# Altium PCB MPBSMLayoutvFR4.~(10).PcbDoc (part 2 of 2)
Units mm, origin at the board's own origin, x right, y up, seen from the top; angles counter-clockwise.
Board outline 131.7 x 110.39 mm, 4 copper layers (Top Layer, Power, GroundPlane, Bottom Layer), stack 2.286 mm thick; 156 components, 77 nets, 429 pads, 117 vias.
Unrouted connection lines stored in the file: 25.
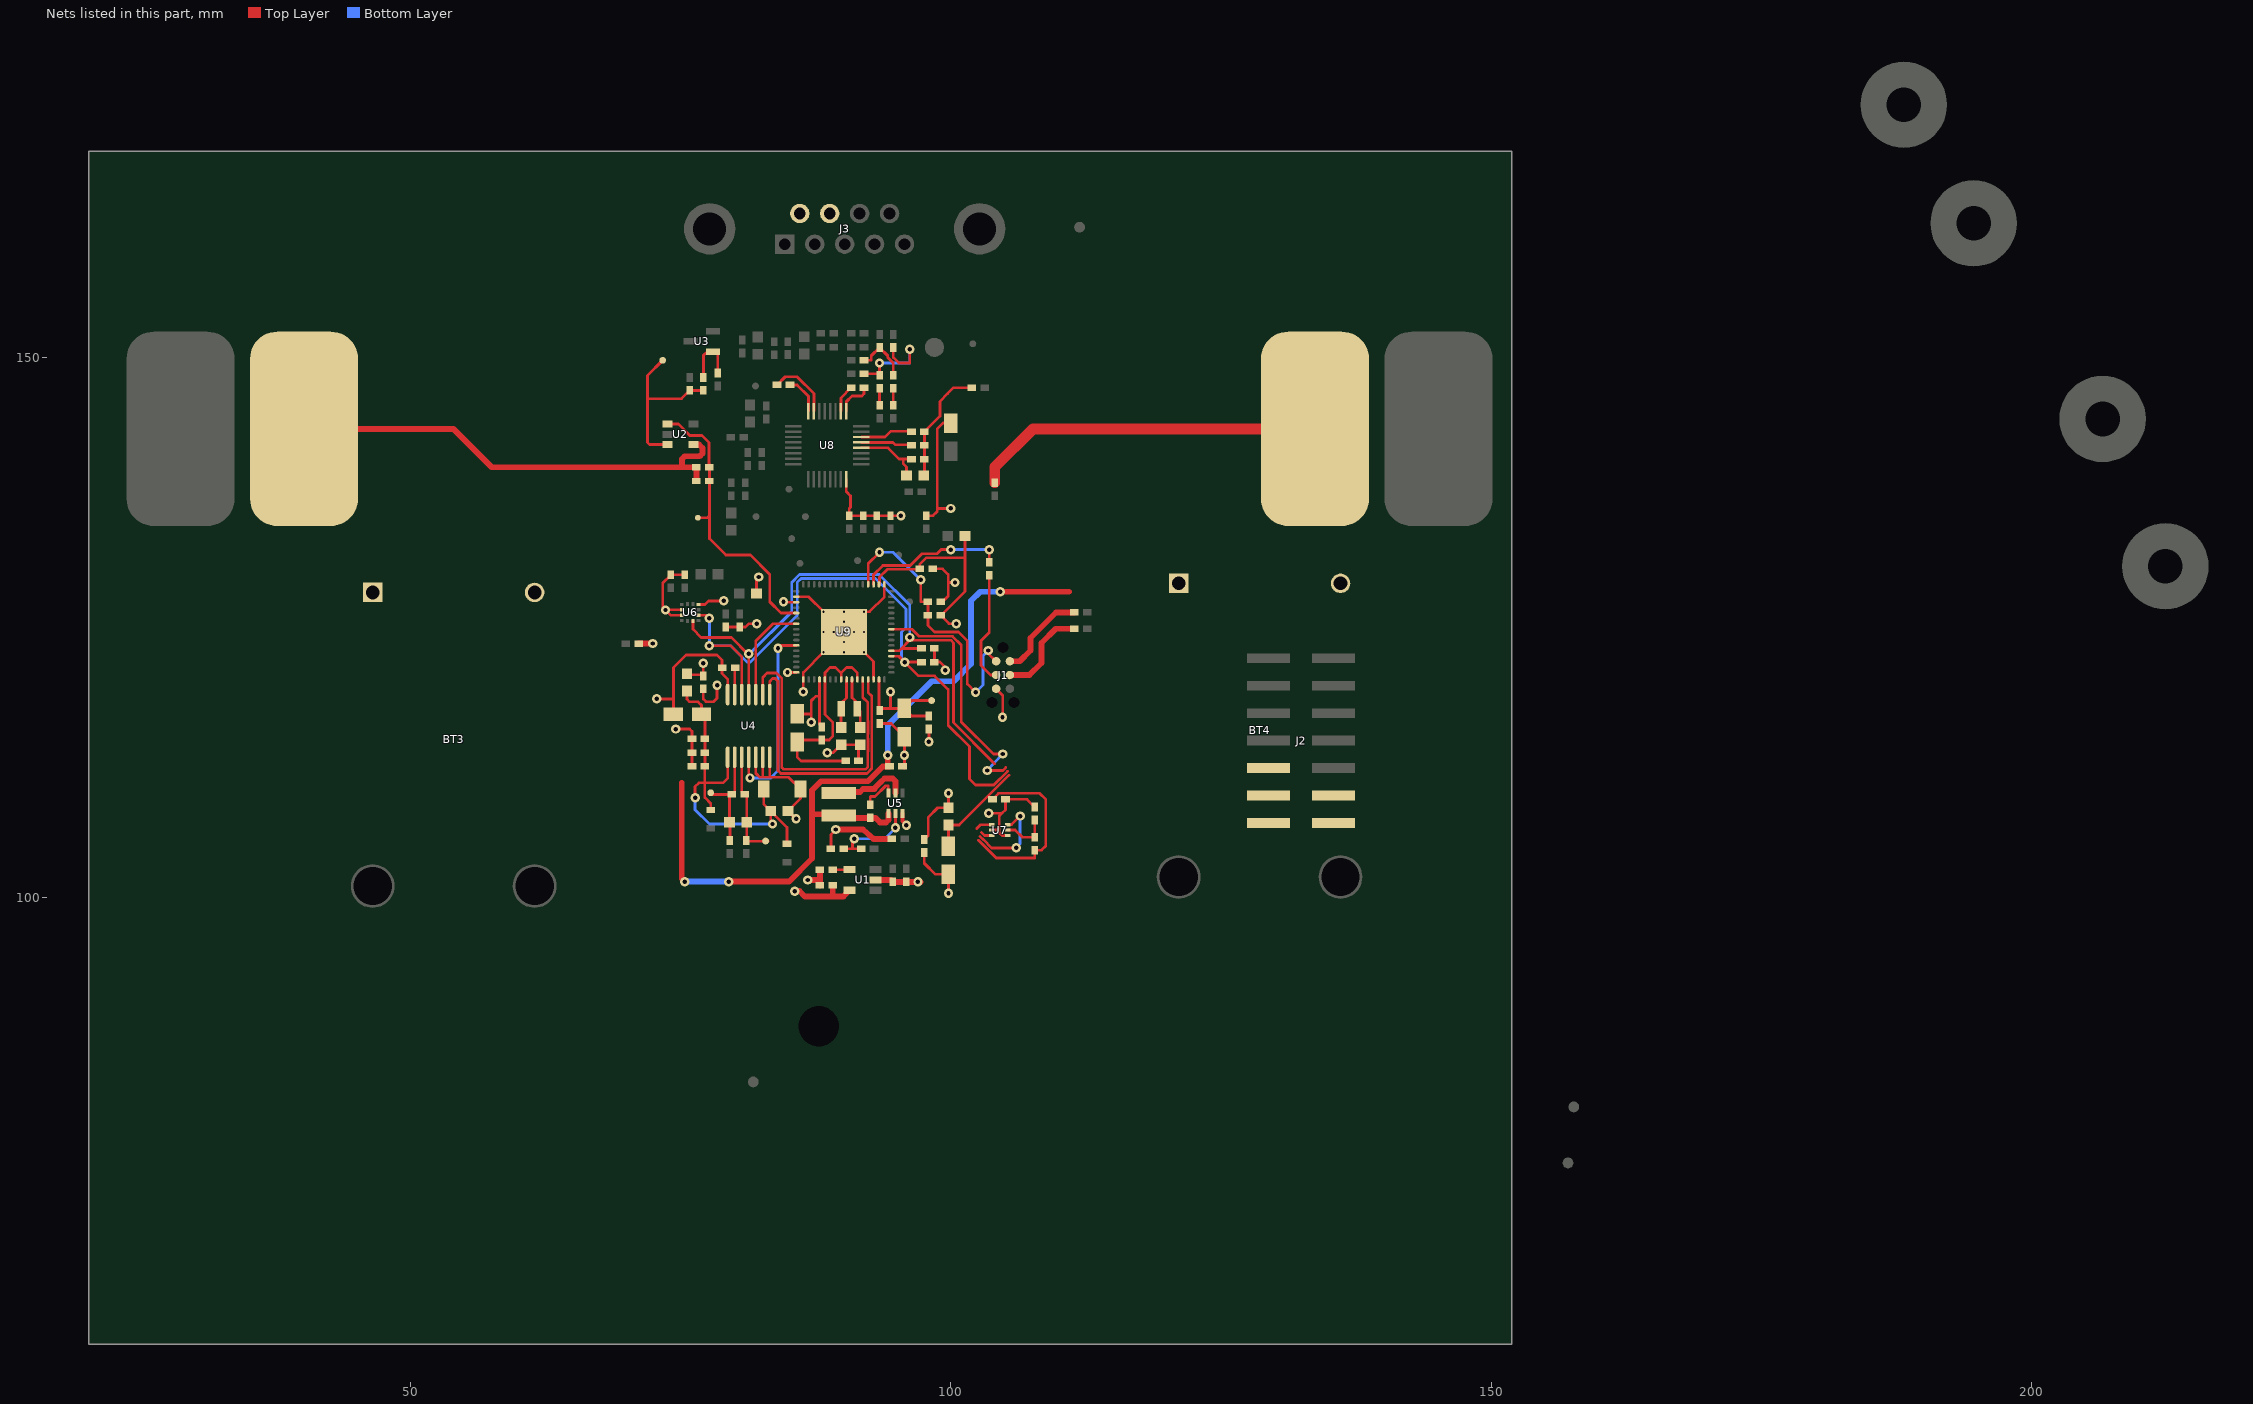
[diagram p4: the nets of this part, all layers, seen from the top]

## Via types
v1: diameter 0.864, hole 0.406, Top Layer to Bottom Layer, 104 vias
v2: diameter 0.5, hole 0.2, Top Layer to Bottom Layer, 13 vias

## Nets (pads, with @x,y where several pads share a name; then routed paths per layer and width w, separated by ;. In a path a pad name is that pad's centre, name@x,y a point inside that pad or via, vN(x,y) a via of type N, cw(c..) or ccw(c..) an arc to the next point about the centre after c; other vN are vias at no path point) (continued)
BOOST_INPUT: BT3.1 BT4.1 C34.1 L7.1 R16.1 U5.1 | length 73.3
  Top Layer w0.254: L7.1@89.612,107.681 L7.1@89.621,107.672 ; v1(94.158,113.132) v1@94.32,112.97
  Top Layer w0.5: 75.108,110.592 75.108,101.702 v1(75.362,101.448)
  Top Layer w0.54: v1(79.426,101.448) 85.014,101.448 87.147,103.581 87.147,109.906 87.986,110.744 92.329,110.744 93.701,112.116 C34.1@94.32,112.116 ; 87.147,107.696 L7.1@89.612,107.681 ; L7.1@89.832,107.35 R16.1@92.532,107.35 93.018,107.35 93.434,106.934 94.005,106.934 94.219,107.148 U5.1@94.219,107.762 ; C34.1@94.158,112.278 v1(94.158,113.132) ; v1(104.572,128.287) 110.921,128.287
  Bottom Layer w0.54: v1(75.362,101.448) v1(79.426,101.448) ; v1(94.158,113.132) 94.158,115.926 98.222,119.99 100.254,119.99 101.87,121.606 101.87,127.448 102.709,128.287 v1(104.572,128.287)
DVCC: 1.1 C1.1 C5.1 C6.1 C10.1 C14.1 C18.1 L1.1 L2.1 L3.1 L5.1 R1.1 R6.2 R31.1 R32.1 U1.5 U9.18 U9.35 U9.48 U9.63 | length 53
  Top Layer w0.254: L1.1@75.362,120.59 76.94,120.59 C10.1@76.964,120.613 ; C10.1@77.089,120.488 v1(77.089,121.666) ; L3.1@82.004,128.118 82.004,129.426 v1(82.22,129.642) ; v1@84.55,127.312 U9.35@85.694,127.312 ; v1(84.876,120.812) U9.48@85.694,120.812 ; U9.63@93.345,120.162 93.345,117.339 C6.1@93.396,117.288 ; U9.18@93.345,128.962 93.391,129.008 93.391,129.637 94.11,130.356 97.066,130.356 C18.1@97.114,130.404 97.114,130.82 97.714,131.42 101.27,131.42 ; C6.1@93.588,117.48 C1.1@95.682,117.48 ; 94.415,117.483 v1(94.415,119.027) ; C14.1@97.538,105.35 97.917,105.728 97.917,107.414 98.788,108.286 L2.1@99.779,108.286 v1(99.779,109.621) ; R1.1@97.968,116.78 96.382,116.78 C1.1@95.682,117.48 ; 1.1@98.222,118.212 96.414,118.212 C1.1@95.682,117.48 ; R32.1@98.476,123.038 R31.1@98.476,121.768 98.984,121.768 99.492,121.26 v1(99.492,121.006) ; v1(100.508,125.324) 99.838,125.324 R6.2@99.076,126.086 101.308,128.318 L5.1@101.308,133.452
  Top Layer w0.54: v1(85.547,100.559) v1@85.954,100.559 ; 85.979,100.584 86.487,100.076 89.073,100.076 ; C5.1@89.073,101.092 89.073,100.076 ; U1.5@90.621,100.65 90.047,100.076 89.073,100.076
  other v1: 84.506,127.356
EL_GSR1: C26.2 J3.7 R10.1 TP2.1 U2.4 | length 43.3
  Top Layer w0.254: U2.4@76.17,141.9 76.682,141.9
  Top Layer w0.54: TP2.1@40.132,143.358 53.95,143.358 57.506,139.802 R10.1@76.448,139.802 C26.2@76.448,138.532 ; 75.108,139.852 75.108,140.564 75.362,140.818 76.748,140.818 77.002,141.072 77.002,141.58 76.682,141.9
EL_GSR2: J3.6 R9.2 TP1.1 | length 32.6
  Top Layer w1: R9.2@104.064,138.37 104.064,139.827 107.594,143.358 TP1.1@133.706,143.358
GND: BT3.2 BT4.2 C1.2 C3.2 C4.2 C5.2 C6.2 C8.2 C9.2 C10.2 C11.2 C12.2 C13.2 C14.2 C15.2 C16.2 C17.2 C18.2 C19.2 C20.2 C21.2 C25.2 C27.2 C28.2 C29.1 C32.2 C33.2 C34.2 C35.2 C36.2 C37.2 C38.2 C41.2 C42.2 C58.2 C59.2 J1.6 J2.6 R2.1 R3.1 R17.1 U1.2 U4.5 U4.6 U4.7 U4.14 U5.3 U6.4 U6.8 U6.9 U7.2 U7.4 U8.24 U9.17 U9.34 U9.49 U9.62 U9.65 | length 145.9
  Top Layer w0.254: v1(72.771,118.364) 74.316,118.364 ; C9.2@74.316,116.942 74.316,118.364 ; v1(74.549,115.57) 75.819,115.57 76.032,115.357 C27.2@76.032,114.656 C11.2@76.032,113.386 C28.2@76.032,112.116 ; U6.9@75.095,126.111 74.067,126.111 v1(73.584,126.594) ; U6.8@75.095,126.611 73.601,126.611 v1(73.584,126.594) ; C37.2@75.362,129.847 C16.2@74.092,129.847 73.33,129.085 73.33,126.848 v1(73.584,126.594) ; U6.4@76.645,127.111 77.249,127.111 77.571,127.433 v1(78.99,127.433) ; C10.2@77.089,119.288 77.089,118.364 77.343,118.11 78.047,118.11 78.359,118.422 v1(78.359,119.634) ; C36.2@79.172,125.024 C17.2@80.442,125.024 80.997,125.024 81.297,125.324 v1(82.042,125.324) ; U4.14@79.337,118.764 79.337,120.193 78.826,120.704 C29.1@78.826,121.26 78.826,121.961 78.359,122.428 75.484,122.428 74.316,121.26 74.316,118.364 ; U4.5@81.937,112.964 81.937,111.484 82.321,111.1 83.236,111.1 ; 82.587,111.137 U4.6@82.587,112.964 ; U4.7@83.237,112.964 83.236,111.1 ; v1(85.67,107.266) 85.645,107.266 C33.2@84.92,107.991 86.074,109.145 C32.2@86.074,110.023 84.997,111.1 83.236,111.1 ; U9.34@85.694,127.812 86.844,127.812 v2(88.219,126.437) v2(90.094,124.562) ; v1(86.343,119.033) U9.49@86.343,120.162 86.343,120.811 v2(88.219,122.687) v2(90.094,124.562) ; v1(86.741,101.6) v1@86.754,101.613 ; v1(88.57,113.386) 89.116,113.386 89.84,114.11 C58.2@91.618,114.11 ; R17.1@88.894,104.496 88.894,105.812 v1(89.356,106.274) ; U8.24@90.32,138.704 90.32,137.544 90.702,137.162 90.702,136.099 90.602,135.999 C42.2@90.602,135.322 C41.2@91.872,135.322 C19.2@93.142,135.322 C20.2@94.412,135.322 v1@95.317,135.322 ; R2.1@91.456,112.624 C58.2@91.456,113.948 ; U9.62@92.844,120.162 92.844,121.811 v2(91.969,122.687) v2(90.094,124.562) ; C6.2@93.396,115.888 C6.2@93.396,116.088 94.474,116.088 C1.2@95.682,114.88 95.7,114.861 v1(95.7,113.132) 95.7,112.296 C34.2@95.52,112.116 C34.2@95.682,111.954 ; U9.17@93.845,128.962 93.845,127.805 92.477,126.437 v2(91.969,126.437) v2(90.094,124.562) ; C3.2@94.447,101.6 C3.2@94.62,101.428 ; v1(96.952,101.448) 96.952,101.194 v1@97.186,101.428 ; C14.2@97.538,104.15 97.538,103.147 98.564,102.122 C12.2@99.779,102.122 v1(99.779,100.374) ; C21.2@97.714,135.322 98.365,135.322 98.73,135.687 98.73,143.358 99.268,143.896 C15.2@100,143.896 C15.2@100,144.374 ; C18.2@98.314,130.404 99.238,130.404 99.746,129.896 99.746,129.134 ; 98.73,135.992 v1(100,135.992) ; C25.2@99.076,127.356 99.238,127.356 99.746,127.864 99.746,129.134 ; v1(100.381,129.134) 99.746,129.134 ; v1(103.5,107.783) 104.745,107.783 ; U7.2@103.779,106.221 104.449,106.221 ; J1.6@104.191,119.304 104.8,118.694 104.8,116.688 v1(104.775,116.662) ; U7.4@105.279,105.721 104.724,105.721 104.474,105.971 104.474,107.512 104.745,107.783 ; C38.2@107.757,108.352 107.041,109.068 C13.2@105.055,109.068 105.055,108.093 104.745,107.783
  Top Layer w0.354: U5.3@95.519,107.762 95.519,107.046 v1(95.885,106.68)
  Top Layer w0.54: R3.1@71.094,123.489 v1(72.397,123.489) ; v1@86.754,101.613 87.873,101.613 ; C5.2@87.873,101.092 87.873,101.613 ; C8.2@87.873,102.54 87.873,101.613 ; v1(89.356,106.274) 90.672,106.274 91.872,106.274 92.837,105.41 C35.2@94.573,105.41 ; U1.2@93.021,101.6 C3.2@94.447,101.6 ; C3.2@94.62,101.428 C4.2@95.89,101.428 v1@97.186,101.428
  other v1: 95.377,135.322
  other v2: 90.094,122.687 90.094,123.624 88.219,124.562 89.156,124.562 91.031,124.562 91.969,124.562 90.094,125.499 90.094,126.437
GSR_ANALOG_OUTPUT: 2.1 C26.1 R10.2 U2.1 U9.37 | length 26.9
  Top Layer w0.254: U2.1@73.77,143.8 74.776,143.8 75.828,142.748 76.945,142.748 77.606,142.088 77.606,140.14 77.648,140.098 R10.2@77.648,139.802 C26.1@77.648,138.532 77.648,135.23 ; 2.1@76.581,135.128 77.546,135.128 ; 77.546,135.23 77.648,135.23 ; U9.37@85.694,126.312 84.28,126.312 83.236,127.356 83.236,129.896 81.458,131.674 79.172,131.674 77.648,133.198 77.648,135.23
JTAG_TCK: J1.4 J2.4 R7.1 | length 10.4
  Top Layer w0.254: R7.1@103.556,129.804 103.556,124.511 102.794,123.749 102.794,121.463 103.683,120.574 J1.4@104.191,120.574
JTAG_TDO/TDI: C25.1 J1.2 J2.2 R6.1 U9.20 | length 28.1
  Top Layer w0.254: U9.20@92.344,128.962 92.344,130.876 v1(93.396,131.928) ; v1(97.206,129.388) 97.206,127.356 C25.1@97.876,127.356 R6.1@97.876,126.086 97.876,125.162 98.476,124.562 100.702,124.562 101.524,123.74 101.524,119.736 v1(102.286,118.974) ; v1(103.454,122.843) 103.454,122.58 J1.2@104.191,121.844
  Bottom Layer w0.254: v1(93.396,131.928) 94.666,131.928 v1(97.206,129.388) ; v1(102.286,118.974) 102.972,119.659 102.972,122.36 v1(103.454,122.843)
JTAG_TEST/SBWTCK: R7.2 U9.19 | length 13.7
  Top Layer w0.254: U9.19@92.844,128.962 92.844,129.852 93.702,130.71 96.242,130.71 97.333,131.801 98.728,131.801 99.109,132.182 v1(100,132.182) ; R7.2@103.556,131.004 v1(103.556,132.182)
  Bottom Layer w0.254: v1(100,132.182) v1(103.556,132.182)
JTAG_VCC_TARGET_IN: J1.3 J2.3 R5.1 | length 8.8
  Top Layer w0.54: J1.3@105.461,120.574 107.264,120.574 108.382,121.691 108.382,122.707 108.382,123.546 109.697,124.861 R5.1@111.433,124.861
JTAG_VCC_TOOL_OUT: J1.1 J2.1 R4.1 | length 8.5
  Top Layer w0.54: J1.1@105.461,121.844 106.375,121.844 107.366,122.834 107.366,124.003 109.728,126.365 R4.1@111.414,126.365
MSP_AVCC: C2.1 C7.1 R1.2 U9.52 | length 9.3
  Top Layer w0.254: C2.1@86.095,116.972 87.076,116.972 ; v1(87.076,116.21) 87.076,116.972 ; C7.1@87.843,115.982 87.843,118.618 ; U9.52@87.843,120.162 87.843,118.618 ; v1(97.968,114.402) R1.2@97.968,115.58 ; 87.076,116.972 87.076,118.191 87.503,118.618 87.843,118.618
MSP_AVSS: C2.2 C7.2 R2.2 U9.53 U9.56 U9.59 | length 20.5
  Top Layer w0.254: C2.2@85.776,114.372 85.776,112.979 86.131,112.624 R2.2@90.256,112.624 ; C2.2@85.968,114.564 C7.2@88.062,114.564 88.732,114.564 89.078,114.91 89.078,116.18 88.343,116.914 U9.53@88.343,120.162 88.343,120.779 88.824,121.26 89.332,121.26 89.836,120.756 ; U9.56@89.844,120.162 89.844,120.756 90.348,121.26 90.856,121.26 91.344,120.771 U9.59@91.344,120.162
MSP_LFXIN: C59.1 U9.57 Y1.1 | length 4.1
  Top Layer w0.254: C59.1@89.84,115.71 89.84,117.438 Y1.1@89.852,117.45 ; Y1.1@89.852,117.97 90.344,118.462 U9.57@90.344,120.162
MSP_LFXOUT: C58.1 U9.58 Y1.2 | length 4.3
  Top Layer w0.254: U9.58@90.844,120.162 90.844,118.477 Y1.2@91.352,117.97 ; Y1.2@91.352,117.45 91.618,117.184 C58.1@91.618,115.71
MSP_P1.0_INT: U4.10 U9.39 | length 9.4
  Top Layer w0.254: U4.10@81.937,118.764 81.937,123.749 ; 81.952,123.749 83.515,125.312 U9.39@85.694,125.312
MSP_P2.7_INT: U7.3 U9.9 | length 24.2
  Top Layer w0.254: U9.9@94.494,124.812 96.417,124.812 97.075,124.154 100.154,124.154 100.962,123.346 100.962,116.234 103.937,113.259 v1(104.8,113.259) ; 102.841,105.989 103.109,105.721 U7.3@103.779,105.721 ; v1@103.361,111.743 104.822,111.743 105.09,112.011
  Bottom Layer w0.254: v1(103.353,111.735) v1(104.8,113.259)
MSP_P4.0_INT: U4.9 U9.60 | length 28.4
  Top Layer w0.254: U4.9@82.587,118.764 82.587,120.356 82.982,120.752 83.849,120.752 84.352,120.248 84.352,112.016 84.506,111.862 92.126,111.862 92.31,112.046 92.31,113.506 92.32,113.516 92.32,114.704 92.31,114.713 92.31,115.106 92.32,115.116 92.32,116.304 92.31,116.313 92.31,118.027 91.844,118.493 U9.60@91.844,120.162
MSP_P4.1_INT: U4.8 U9.61 | length 27.8
  Top Layer w0.254: U4.8@83.237,118.764 83.237,119.99 83.49,120.244 83.744,120.244 83.998,119.99 83.998,111.718 84.262,111.454 92.226,111.454 ; 92.226,111.461 92.664,111.9 92.664,113.36 92.674,113.369 92.674,118.612 92.344,118.942 U9.61@92.344,120.162
MSP_P9.3_OUT: U4.4 U9.43 | length 18
  Top Layer w0.254: U4.4@81.287,112.964 81.287,111.169 v1(81.407,111.049) ; v1(83.998,123.038) 84.272,123.312 U9.43@85.694,123.312
  Bottom Layer w0.254: v1(81.407,111.049) 83.329,111.049 83.998,111.718 v1(83.998,123.038)
MSP_UCB0SCL_TMP103_SCL_RF430CL330HCPW_SCL: R32.2 U4.11 U6.12 U7.1 U9.5 | length 56.8
  Top Layer w0.254: U6.12@76.12,125.586 76.12,124.82 76.886,124.054 79.68,124.054 v1@81.236,122.497 ; U4.11@81.287,118.764 v1@81.287,122.447 ; U9.5@94.494,122.812 95.202,122.812 95.428,123.038 ; v1(96.19,124.054) v1@96.19,123.8 ; R32.2@97.114,123.038 95.428,123.038 ; 102.391,106.343 102.768,106.721 U7.1@103.779,106.721 ; 104.044,112.365 103.861,112.547 100.254,116.18 100.254,123.546 100,123.8 v1@96.19,123.8 ; 95.428,123.038 v1@96.19,123.8
  Bottom Layer w0.254: v1(81.278,122.539) 81.287,122.531 81.287,122.447 85.268,126.428 85.268,129.134 86,129.866 93.365,129.866 96.19,127.042 v1(96.19,124.054)
MSP_UCB0SDA_TMP103_SDA_RF430CL330HCPW_SDA: R31.2 U4.12 U6.2 U7.6 U9.4 | length 70.6
  Top Layer w0.254: U6.2@76.645,126.111 77.369,126.111 v1(77.648,125.832) ; v1(77.648,123.292) 79.594,123.292 80.653,122.233 80.653,118.78 U4.12@80.637,118.764 ; U9.4@94.494,122.312 95.174,122.312 v1(95.718,121.768) ; R31.2@97.276,121.768 v1(95.718,121.768) ; 102.694,105.635 102.998,105.332 103.005,105.332 103.767,104.57 v1(106.053,104.57) ; 105.236,111.657 103.968,110.388 102.286,110.388 101.714,110.96 101.714,113.957 99.746,115.926 99.746,119.228 98.476,120.498 96.988,120.498 v1(95.718,121.768) ; U7.6@105.279,106.721 105.613,106.721 v1(106.409,107.516)
  Bottom Layer w0.254: v1(77.648,125.832) v1(77.648,123.292) 79.594,123.292 81.118,121.768 81.458,121.768 85.776,126.086 85.776,129.134 86.154,129.512 93.017,129.512 95.836,126.694 95.836,124.97 95.428,124.562 95.428,122.058 v1(95.718,121.768) ; v1(106.053,104.57) 106.409,104.925 v1(106.409,107.516)
Net3_1: 3.1 R11.1 R12.2 U2.3 | length 15.6
  Top Layer w0.254: 71.922,146.152 75.059,146.152 R12.2@75.824,146.917 R11.1@77.094,146.917 ; 3.1@73.33,149.708 71.922,148.3 71.922,142.088 72.11,141.9 U2.3@73.77,141.9
Net4_1: 4.1 C30.1 C31.1 R13.1 U4.2 | length 9.9
  Top Layer w0.254: 4.1@77.77,109.676 77.932,109.515 C31.1@79.71,109.515 ; R13.1@79.548,105.255 79.548,106.903 C30.1@79.51,106.941 79.51,109.315 C31.1@79.71,109.515 ; U4.2@79.987,112.964 79.987,109.791 C31.1@79.71,109.515
Net5_1: 5.1 C30.2 C31.2 R14.1 U4.3 | length 9.9
  Top Layer w0.254: U4.3@80.637,112.964 80.637,109.788 C31.2@80.91,109.515 81.11,109.315 C30.2@81.11,106.941 81.11,105.293 81.207,105.197 5.1@83.104,105.197
NetC8_1: C8.1 U1.4 | length 1.6
  Top Layer w0.254: C8.1@89.068,102.54 89.078,102.55 U1.4@90.621,102.55
NetC29_2: C29.2 U4.13 | length 2.5
  Top Layer w0.254: U4.13@79.987,118.764 79.987,121.22 C29.2@80.026,121.26
NetC38_1: C38.1 R18.1 U7.5 | length 4.3
  Top Layer w0.254: U7.5@105.279,106.221 105.951,106.221 106.615,105.558 R18.1@107.757,105.558 C38.1@107.757,107.152
NetC43_1: C43.1 R19.2 R20.2 R21.2 R22.1 | length 10.9
  Top Layer w0.254: C43.1@97.552,139.094 R20.2@97.552,140.564 R21.2@97.552,141.834 97.552,141.876 R19.2@97.552,143.104 98.984,144.536 98.984,145.898 99.704,146.618 100.254,147.168 R22.1@101.94,147.168
NetC43_2: C43.2 R20.1 U8.28 | length 6.7
  Top Layer w0.254: U8.28@91.719,141.603 94.172,141.603 95.212,140.564 95.58,140.564 ; C43.2@95.898,139.04 95.898,139.818 95.58,140.135 95.58,140.564 ; R20.1@96.352,140.564 95.58,140.564
NetC45_1: C45.1 U8.2 | length 2.6
  Top Layer w0.254: U8.2@89.82,145.003 89.82,146.224 C45.1@90.764,147.168
NetC45_2: C45.2 U8.1 | length 3.4
  Top Layer w0.254: U8.1@90.32,145.003 90.32,145.87 90.856,146.406 91.757,146.406 91.964,146.612 C45.2@91.964,147.168
NetC46_2: C46.2 C48.2 C49.2 | length 10.4
  Top Layer w0.254: C46.2@91.964,148.45 C49.2@93.267,148.45 ; C49.2@93.396,148.322 v1(93.396,149.454) ; C48.2@94.666,150.886 94.671,150.88 94.671,149.967 95.185,149.454 96.19,149.454 v1(96.19,150.724)
  Bottom Layer w0.254: v1(93.396,149.454) 96.19,149.454 v1(96.19,150.724)
NetC47_1: C47.1 U8.8 | length 3.5
  Top Layer w0.254: C47.1@85.106,147.422 85.776,147.422 86.82,146.378 U8.8@86.82,145.003
NetC47_2: C47.2 U8.7 | length 6
  Top Layer w0.254: C47.2@83.906,147.422 84.668,148.184 85.776,148.184 87.32,146.64 U8.7@87.32,145.003
NetC49_1: C49.1 R26.1 | length 1.6
  Top Layer w0.254: R26.1@93.396,145.528 C49.1@93.396,147.122
NetC52_2: C52.2 C53.2 C54.2 | length 5.3
  Top Layer w0.254: C54.2@91.964,149.708 92.634,149.708 92.634,150.124 C52.2@93.396,150.886 94.158,150.124 94.158,149.962 94.666,149.454 C53.2@94.666,148.322
NetC53_1: C53.1 R27.1 | length 1.6
  Top Layer w0.254: R27.1@94.666,145.528 C53.1@94.666,147.122
NetL7_2: L7.2 U5.5 | length 5.5
  Top Layer w0.254: 92.939,110.033 92.939,110.084
  Top Layer w0.54: L7.2@91.059,109.752 91.591,109.752 91.872,110.033 92.939,110.033 ; 92.939,110.084 93.519,110.664 93.853,110.998 94.615,110.998 94.869,110.744 U5.5@94.869,109.662
NetR8_1: R8.1 R11.2 U3.1 | length 5.5
  Top Layer w0.254: R11.2@77.094,148.117 77.094,150.17 77.46,150.536 78.41,150.536 R8.1@78.41,148.53
NetR15_1: R15.1 R17.2 U5.2 | length 8.1
  Top Layer w0.254: R17.2@90.094,104.496 90.891,104.496 ; v1(91.059,105.41) 90.891,105.242 90.891,104.496 ; R15.1@91.688,104.496 90.891,104.496 ; v1(94.869,106.426) U5.2@94.869,107.762
  Bottom Layer w0.254: v1(91.059,105.41) 93.853,105.41 v1(94.869,106.426)
NetR16_2: R16.2 U5.6 | length 3.5
  Top Layer w0.254: R16.2@92.532,108.55 92.532,109.271 92.583,109.322 92.964,109.322 93.969,110.327 94.209,110.327 94.209,109.672 U5.6@94.219,109.662
NetR19_1: R19.1 U8.30 | length 4.9
  Top Layer w0.254: U8.30@91.719,142.603 93.911,142.603 94.454,143.146 R19.1@96.352,143.146
NetR21_1: R21.1 U8.29 | length 4.7
  Top Layer w0.254: U8.29@91.719,142.103 94.65,142.103 94.878,141.876 R21.1@96.352,141.876
RF430_DVCC: C9.1 C11.1 C27.1 C28.1 C32.1 C33.1 D1.1 D2.1 L1.2 U4.1 | length 34
  Top Layer w0.254: 75.565,118.512 75.565,118.338 75.811,118.092 76.599,118.092 76.916,117.775 C9.1@76.916,116.942 C9.1@77.14,117.166 ; v1(76.327,109.22) 76.327,110.236 76.683,110.592 77.226,110.592 ; C28.1@77.232,112.116 C11.1@77.232,113.386 C27.1@77.232,114.656 C9.1@77.232,116.626 ; C28.1@77.324,112.024 77.226,111.926 77.226,110.592 ; D1.1@77.77,108.079 77.77,108.691 77.226,109.235 77.226,110.592 ; U4.1@79.337,112.964 79.337,111.01 78.918,110.592 77.226,110.592 ; C32.1@82.674,110.023 82.674,108.637 C33.1@83.32,107.991 ; v1(83.49,106.782) 83.32,106.951 C33.1@83.32,107.991 ; D2.1@84.836,104.989 84.836,106.475 C33.1@83.32,107.991
  Bottom Layer w0.254: v1(76.327,109.22) 76.327,108.102 77.648,106.782 v1(83.49,106.782)
TMP_DVCC: C12.1 C13.1 L2.2 R18.2 | length 27
  Top Layer w0.254: C12.1@99.779,104.722 L2.2@99.779,106.686 100.766,106.686 105.383,111.303 ; 102.548,105.281 104.199,103.63 107.757,103.63 R18.2@107.757,104.358 108.381,104.358 108.792,104.768 108.792,109.049 108.223,109.618 104.405,109.618 C13.1@103.855,109.068
pads on no net: BT3.3 BT3.4 BT4.3 BT4.4 FID1.1 FID2.1 FID3.1 H1.0 H2.0 H3.0 H4.0 H5.1 H6.1 H7.1 H8.1 H9.0 H10.0 H11.0 H12.0 J1.5 J1.MH1 J1.MH2 J1.MH3 J2.5 J2.7 J2.8 J2.9 J2.10 J2.11 J2.12 J2.13 J2.14 J3.3 J3.5 J3.8 J3.9 U3.3 U6.10 U8.17 U9.1 U9.2 U9.3 U9.6 U9.7 U9.8 U9.10 U9.11 U9.12 U9.13 U9.15 U9.21 U9.22 U9.23 U9.24 U9.36 U9.40 U9.41 U9.42 U9.44 U9.45 U9.46 U9.47 U9.50 U9.51 U9.54 U9.55 U9.64
copper on no net: | length 0.5
  Top Layer w0.254: 104.521,124.206 v1(104.521,124.714)

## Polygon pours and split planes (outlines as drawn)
DVCC on Power (split plane): 102.41,142.288 102.41,131.727 101.775,131.092 78.667,131.092 78.031,131.727 78.031,133.144 79.225,134.338 93.142,134.338 93.191,134.348 93.233,134.376 98.313,139.456 98.341,139.498 98.351,139.548 98.351,142.796 98.76,143.205 101.494,143.205
DVCC on Power (split plane): 87.587,117.065 87.932,116.61 87.932,112.624 87.942,112.574 87.97,112.532 88.012,112.504 88.062,112.494 96.028,112.494 96.077,112.504 96.119,112.532 97.043,113.456 97.071,113.498 97.081,113.548 97.081,115.796 98.844,115.796 98.844,115.57 98.844,113.937 98.384,113.477 97.107,112.2 96.644,111.737 86.803,111.737 86.159,112.41 86.159,116.653 86.574,117.089
DVCC on Power (split plane): 90.726,154.534 90.685,146.998 81.966,147.043 81.941,147.038 81.917,147.033 81.916,147.033 81.896,147.019 81.875,147.006 81.875,147.005 81.874,147.005 81.86,146.984 81.846,146.964 81.846,146.963 81.841,146.939 81.836,146.914 81.836,143.104 81.846,143.054 81.874,143.012 81.916,142.984 81.966,142.974 86.662,142.974 86.662,141.201 83.49,141.201 83.44,141.191 83.398,141.163 83.37,141.121 83.36,141.072 83.36,135.359 77.218,135.359 77.218,139.09 77.209,139.14 77.181,139.182 74.983,141.379 74.983,145.59 78,148.607 79.139,148.607 79.164,148.612 79.188,148.616 79.188,148.617 79.189,148.617 79.209,148.631 79.23,148.644 79.23,148.645 79.231,148.645 79.244,148.665 79.258,148.686 79.259,148.687 79.263,148.711 79.268,148.736 79.301,154.658 90.726,154.658
DVCC on Power (split plane): 151.407,158.471 151.407,59.159 20.729,59.159 20.729,168.527 151.407,168.527
ADS_AVSS on GroundPlane (split plane): 151.407,158.471 151.407,128.806 102.161,128.806 102.161,137.008 102.151,137.057 102.123,137.099 102.081,137.127 102.032,137.137 98.984,137.137 98.934,137.127 98.892,137.099 98.864,137.057 98.854,137.008 98.854,135.765 96.522,135.765 96.522,136.398 96.513,136.448 96.485,136.49 96.443,136.518 96.393,136.527 89.454,136.527 89.439,136.524 89.423,136.524 89.414,136.52 89.404,136.518 89.391,136.509 89.377,136.503 77.707,127.993 20.729,128.018 20.729,168.527 151.407,168.527
GND on GroundPlane (split plane): 101.902,128.676 101.912,128.627 101.94,128.585 101.982,128.557 102.032,128.547 151.407,128.547 151.407,59.159 20.729,59.159 20.729,127.759 77.75,127.734 77.799,127.744 77.841,127.772 77.844,127.776 77.86,127.784 89.496,136.269 96.264,136.269 96.264,135.636 96.273,135.586 96.301,135.544 96.343,135.516 96.393,135.507 98.984,135.507 99.033,135.516 99.075,135.544 99.103,135.586 99.113,135.636 99.113,136.878 101.902,136.878

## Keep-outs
Keep-Out Layer:
  text ".Layer_Name" at 157.226,108.306 h1.52

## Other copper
Top Layer:
  text ".Layer_Name" at 157.226,156.566 h1.52
Bottom Layer:
  text ".Layer_Name" at 157.226,154.026 h1.52
  text "SVN:" at 49.721,114.91 h1.52 r90
  text ".VersionControl_RevNumber" at 49.721,107.823 h1.52 r90
  text "UL94V-0" at 55.753,69.774 h1.52 r90
Power (plane layer: these items are gaps in the copper):
  rectangle: 74.854,69.952 100.254,99.67
  lines w0.254: 98.974,115.57 98.974,115.926 ; 98.974,115.926 98.57,115.926 96.952,115.926 96.952,113.548 96.028,112.624 88.281,112.624 88.062,112.624 88.062,116.654 87.652,117.193 86.52,117.219 86.03,116.705 86.03,112.358 86.748,111.608 92.216,111.608 96.698,111.608 97.198,112.108 98.476,113.386 98.974,113.884 98.974,115.926 ; 74.854,141.326 77.089,139.09 77.089,135.23 81.262,135.23 83.49,135.23 83.49,141.072 86.792,141.072 86.792,143.104 81.966,143.104 81.966,146.914 90.814,146.868 90.856,154.534 90.856,154.788 79.172,154.788 79.139,148.736 77.946,148.736 74.854,145.644 74.854,141.326 ; 77.902,131.674 77.902,133.198 79.172,134.468 93.142,134.468 98.222,139.548 98.222,142.85 98.706,143.334 101.547,143.334 102.54,142.342 102.54,131.674 101.829,130.962 78.613,130.962 77.902,131.674
GroundPlane (plane layer: these items are gaps in the copper):
  rectangle: 74.854,69.952 100.254,99.67
  lines w0.254: 20.117,127.889 77.75,127.864 ; 77.784,127.888 89.454,136.398 96.393,136.398 96.393,135.636 98.984,135.636 98.984,137.008 102.032,137.008 102.032,128.676 151.79,128.676

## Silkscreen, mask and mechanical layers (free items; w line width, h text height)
Top Overlay:
  region: 96.393,77.724 96.393,85.344 93.853,85.344 93.853,77.724
  lines w1: 73.939,70.891 101.067,70.891 101.067,98.222 73.939,98.222 73.939,70.891
  lines w2: 21.006,133.325 44.806,133.325 150.317,133.325 ; 48.997,60.96 48.997,132.918 48.997,167.716 ; 125.705,61.646 125.705,167.157
  text "GSR" at 130.124,153.289 h4
  text "ECG" at 141.503,153.238 h4
  text "ECG" at 24.765,152.806 h4
  text "GSR" at 37.414,152.756 h4
  text "GND" at 46.66,131.318 h1.02
  text "VCC" at 60.173,129.845 h1.02
  text ".Layer_Name" at 157.226,128.626 h1.52
  text "JTAG" at 106.807,126.009 h1.02
  text "BAT" at 110.617,122.987 h1.02
  text "VCC" at 62.052,121.361 h1.02
  text "GND" at 46.914,121.158 h1.02
  text "FOR DEMO PURPOSES ONLY" at 76.556,94.259 h1.02
  text "MPBSM" at 80.137,91.44 h1.02
  text "REV A" at 80.137,89.916 h1.02
  text "TI" at 92.227,87.884 h1.52
  text "©" at 94.869,87.63 h2.67
  text ".CopyrightYear" at 85.217,77.724 h1.52
  text "MADE IN U.S." at 78.867,75.438 h1.52
  text "NFC Antenna" at 80.62,68.504 h2
  text "-" at 50.978,67.666 h1.52 r90
  text "Place phone here" at 52.984,62.84 h10
Bottom Overlay:
  text ".Layer_Name" at 157.226,126.086 h1.52
Top Paste:
  text ".Layer_Name" at 157.226,123.546 h1.52
Bottom Paste:
  text ".Layer_Name" at 157.226,121.006 h1.52
Top Solder:
  text ".Layer_Name" at 157.226,118.466 h1.52
  text ".Layer_Name" at 157.226,115.926 h1.52
Bottom Solder:
  text ".Layer_Name" at 157.226,113.386 h1.52
Drill Guide:
  text ".Layer_Name" at 157.226,110.846 h1.52
M1 Board Outline:
  lines w0.254: 75.362,58.257 101.651,58.257
  text ".Layer_Name" at 157.226,151.486 h1.52
M2 Board Dimensions:
  rectangle: 17.577,32.982 20.752,36.157
  rectangle: 20.752,29.807 30.277,32.982
  lines w0.178: 17.577,32.982 42.977,32.982 ; 20.752,29.807 20.752,36.157 ; 23.927,29.807 23.927,36.157 ; 30.277,29.807 30.277,36.157 ; 36.627,29.807 36.627,36.157 ; 17.577,29.807 42.977,29.807 42.977,36.157 17.577,36.157 17.577,29.807
  text ".Layer_Name" at 18.034,37.338 h1.52
M3 3D STEP Top:
  text ".Layer_Name" at 157.226,148.946 h1.52
M4 3D STEP Bottom:
  text ".Layer_Name" at 157.226,146.406 h1.52
M5 Assembly Top:
  lines w0.254: 10.16,16.607 177.8,16.607 ; 10.16,21.772 177.851,21.772 ; 10.16,26.937 10.16,11.443 111.887,11.443 177.851,11.443 177.851,26.937 10.173,26.937 10.173,11.443 50.19,11.443 ; 72.771,11.443 72.771,26.937 ; 104.953,21.772 104.953,26.937 ; 126.289,21.772 126.289,26.937 ; 142.088,11.278 142.088,16.43
  text "COMPONENTS MARKED 'DNP' SHOULD NOT BE POPULATED." at 46.876,32.144 h1.52
  text "ASSEMBLY VARIANT:" at 46.863,29.21 h1.52
  text ".VariantName" at 73.177,29.21 h1.52
  text "PCB VIEWED FROM TOP SIDE" at 11.773,23.58 h1.52
  text "BOARD #:" at 74.676,23.58 h1.52
  text ".PRJ_Number" at 88.532,23.58 h1.52
  text "REV:" at 109.982,23.58 h1.52
  text ".PCB_Rev" at 117.386,23.58 h1.52
  text "SVN REV:" at 131.267,23.58 h1.52
  text ".VersionControl_RevNumber" at 144.12,23.58 h1.52
  text "IGNORE ->" at 11.773,18.428 h1.52
  text "PLOT NAME =" at 11.773,13.199 h1.52
  text ".plot_File_Name" at 32.233,13.199 h1.52
  text "GENERATED    :" at 74.727,13.199 h1.52
  text ".Print_Date" at 96.812,13.199 h1.52
  text ".Print_Time" at 115.329,13.199 h1.52
  text "TEXAS INSTRUMENTS" at 147.447,13.199 h1.52
M6 Assembly Bottom:
  lines w0.254: 10.147,21.759 177.838,21.759 ; 10.198,16.595 177.838,16.595 ; 45.91,11.265 45.91,16.417 ; 61.709,21.759 61.709,26.924 ; 83.045,21.759 83.045,26.924 ; 115.227,11.43 115.227,26.924 ; 137.808,11.43 177.825,11.43 177.825,26.924 10.147,26.924 10.147,11.43 76.111,11.43 177.838,11.43 177.838,26.924
  text "COMPONENTS MARKED 'DNP' SHOULD NOT BE POPULATED." at 172.568,32.156 h1.52
  text ".VariantName" at 146.05,29.21 h1.52
  text "ASSEMBLY VARIANT:" at 172.441,29.21 h1.52
  text ".VersionControl_RevNumber" at 43.878,23.567 h1.52
  text "SVN REV:" at 56.731,23.567 h1.52
  text ".PCB_Rev" at 70.612,23.567 h1.52
  text "REV:" at 78.016,23.567 h1.52
  text ".PRJ_Number" at 99.466,23.567 h1.52
  text "BOARD #:" at 113.322,23.567 h1.52
  text "PCB VIEWED FROM BOTTOM SIDE" at 176.225,23.567 h1.52
  text "IGNORE ->" at 82.292,18.428 h1.52
  text "TEXAS INSTRUMENTS" at 40.551,13.187 h1.52
  text ".Print_Time" at 72.669,13.187 h1.52
  text ".Print_Date" at 91.186,13.187 h1.52
  text "GENERATED    :" at 113.271,13.187 h1.52
  text ".plot_File_Name" at 155.766,13.187 h1.52
  text "PLOT NAME =" at 176.225,13.187 h1.52
M9 Title Sheet:
  drawing of 57 lines, arcs and shapes, not listed
  text "1" at 36.369,243.091 h1.78
  text "2" at 99.758,243.091 h1.78
  text "3" at 162.988,243.091 h1.78
  text "4" at 226.657,243.091 h1.78
  text "5" at 290.131,243.091 h1.78
  text "6" at 353.758,243.091 h1.78
  text "A" at 6.998,214.058 h1.78
  text "A" at 382.918,214.058 h1.78
  text "B" at 6.998,153.606 h1.78
  text "B" at 382.918,153.606 h1.78
  text ".Layer_Name" at 157.226,143.866 h1.52
  text "C" at 6.998,93.281 h1.78
  text "C" at 382.918,93.281 h1.78
  text "PROJECT TITLE:" at 305.702,46.012 h1.14
  text ".PRJ_Title" at 306.972,42.626 h1.78
  text "DESIGNED FOR:" at 305.702,38.367 h1.14
  text ".PRJ_Customer" at 306.972,34.811 h1.78
  text "D" at 6.998,33.084 h1.78
  text "D" at 382.918,33.084 h1.78
  text "FILE NAME:" at 305.702,30.747 h1.14
  text ".PCB_File_Name_No_Path" at 306.972,27.699 h1.78
  text "Texas Instruments (TI) and/or its licensors do not warrant the accuracy or completeness of this specification" at 179.476,23.588 h1.14
  text "ENGINEER:" at 305.702,23.381 h1.14
  text "LAYOUT BY:" at 343.929,23.381 h1.14
  text "or any information contained therein. TI and/or its licensors do not warrant that this design will meet" at 178.334,20.726 h1.14
  text ".PRJ_Engineer" at 306.972,19.444 h1.78
  text ".PCB_Layout" at 345.211,19.444 h1.78
  text "the specifications, will be suitable for your application or fit for any particular purpose, or will operate in" at 178.334,17.865 h1.14
  text "ALTIUM DESIGNER VERSION:" at 343.929,15.507 h1.14
  text "an implementation. TI and/or its licensors do not warrant that the design is production worthy. You should" at 178.334,15.003 h1.14
  text "completely validate and test your design implementation to confirm the system functionality for your application." at 179.476,12.141 h1.14
  text ".print_Scale" at 306.972,12.12 h1.78
  text ".Application_BuildNumber" at 345.211,12.12 h1.78
  text "1" at 36.369,6.871 h1.78
  text "2" at 99.758,6.871 h1.78
  text "3" at 162.988,6.871 h1.78
  text "4" at 226.657,6.871 h1.78
  text "5" at 290.131,6.871 h1.78
  text "6" at 353.758,6.871 h1.78
M10 Fab Notes:
  drawing of 185 lines, arcs and shapes, not listed
  text "DESIGN INFORMATION" at 332.055,190.348 h1.52
  text "MIN. TRACK WIDTH:" at 315.683,185.776 h1.52
  text "8" at 343.527,185.776 h1.52
  text "MIL" at 347.458,185.776 h1.52
  text "MIN. CLEARANCE:" at 315.683,182.423 h1.52
  text "0.2" at 342.003,182.423 h1.52
  text "mm" at 347.458,182.423 h1.52
  text "MIN. VIA PAD SIZE:" at 315.683,179.07 h1.52
  text "24" at 342.766,179.07 h1.52
  text "MIL" at 347.458,179.07 h1.52
  text "0.05mm (2MIL)" at 333.336,175.471 h1.52
  text "MINIMUM ANNULAR RING" at 307.32,175.362 h1.52
  text "EXTERNAL" at 351.319,175.362 h1.52
  text "PER" at 312.4,172.364 h1.52
  text "IPC-D-275 CLASS 2 LEVEL C" at 317.988,172.364 h1.52
  text "MIL, HOLES" at 355.789,169.512 h1.52
  text "+/-" at 345.821,169.494 h1.52
  text "+/-" at 367.513,169.494 h1.52
  text "REGISTRATION TOLERANCES:" at 307.32,169.367 h1.52
  text "METAL" at 337.795,169.367 h1.52
  text "5" at 352.43,169.367 h1.52
  text "3" at 373.588,169.367 h1.52
  text "MIL" at 376.541,169.367 h1.52
  text "MATERIAL:" at 305.421,164.047 h1.52
  text "FR-4 High Tg" at 330.477,160.482 h1.52
  text "FR-408" at 316.115,160.265 h1.52
  text "X" at 326.579,160.265 h1.52
  text "OTHER" at 353.91,160.265 h1.52
  text "62 MIL (1.6mm) +/-10%" at 324.245,156.132 h1.52
  text "THICKNESS:" at 307.32,156.023 h1.52
  text "X" at 320.99,156.023 h1.52
  text "OTHER" at 356.882,156.023 h1.52
  text "TOLERANCE:" at 307.32,152.01 h1.52
  text "X" at 328.639,152.01 h1.52
  text "ANSI IPC-6012 TYPE 3 CLASS 2" at 333.387,152.01 h1.52
  text "OTHER +/-" at 333.387,148.047 h1.52
  text "BOW & TWIST:" at 307.32,144.06 h1.52
  text "X" at 328.639,144.06 h1.52
  text "ANSI IPC-6012 TYPE 3 CLASS 2" at 333.387,144.06 h1.52
  text ".Layer_Name" at 157.226,141.326 h1.52
  text "OTHER +/-" at 333.387,140.034 h1.52
  text "DRILLING:" at 305.421,136.516 h1.52
  text "REFERENCE:" at 307.32,133.544 h1.52
  text "X" at 323.785,133.544 h1.52
  text "AS SHOWN" at 328.535,133.544 h1.52
  text "X" at 346.671,133.544 h1.52
  text "NC_DRILL FILES" at 350.151,133.544 h1.52
  text "PTH MIN COPPER THICKNESS:" at 307.32,129.531 h1.52
  text "X" at 341.616,129.531 h1.52
  text "1MIL" at 345.096,129.531 h1.52
  text "OTHER" at 357.72,129.531 h1.52
  text "BOARD FINISH:" at 305.421,125.492 h1.52
  text "SILKSCREEN:" at 309.364,122.495 h1.52
  text "X" at 333.463,122.495 h1.52
  text "TOP" at 336.663,122.495 h1.52
  text "X" at 346.417,122.495 h1.52
  text "BOTTOM" at 349.643,122.495 h1.52
  text "SILKSCREEN COLOR:" at 310.634,118.26 h1.52
  text "X" at 333.436,118.253 h1.52
  text "WHITE" at 336.663,118.253 h1.52
  text "OTHER" at 349.643,118.253 h1.52
  text "SOLDER RESIST COLOR:" at 309.364,113.935 h1.52
  text "GREEN" at 327.011,109.892 h1.52
  text "BLUE" at 342.023,109.892 h1.52
  text "OTHER" at 355.688,109.892 h1.52
  text "X" at 323.785,109.644 h1.52
  text "IMMERSION GOLD (ENIG)" at 332.371,105.103 h1.52
  text "ENEPIG" at 366.344,105.02 h1.52
  text "SURFACE FINISH:" at 305.421,104.994 h1.52
  text "X" at 327.622,104.994 h1.52
  text "IMM. TIN/SILVER OR EQUIV" at 313.792,101.007 h1.52
  text "OTHER" at 350.151,101.007 h1.52
  text "ARRAY/PANEL:" at 305.421,96.46 h1.52
  text "CUT AND TRIM PER MECH LAYER 1" at 332.371,96.351 h1.52
  text "N.C. ROUTE" at 332.371,92.498 h1.52
  text "X" at 349.617,92.498 h1.52
  text "V. SCORE" at 354.367,92.498 h1.52
  text "CERTIFICATION:" at 305.421,89.018 h1.52
  text "MATERIALS AND WORKMANSHIP FOR ALL PCBS" at 323.836,89.018 h1.52
  text "TO MEET OR EXCEED THE REQUIREMENTS OF:" at 323.836,86.529 h1.52
  text "X" at 314.349,83.061 h1.52
  text "ANSI IPC-A-600F CLASS ->" at 317.88,83.061 h1.52
  text "X" at 359.512,83.061 h1.52
  text "2" at 362.533,83.061 h1.52
  text "1" at 354.532,83.023 h1.52
  text "3" at 371.525,83.023 h1.52
  text "X" at 314.402,79.01 h1.52
  text "UL 94V-0" at 317.88,79.01 h1.52
  text "X" at 335.026,79.01 h1.52
  text "RoHS" at 338.505,79.01 h1.52
  text "OTHER" at 354.873,79.01 h1.52
  text "PER ORDER" at 364.958,79.01 h1.52
  text "ADDITIONAL REQUIREMENTS:" at 305.193,75.302 h1.52
  text "MICROSECTION:" at 307.092,72.381 h1.52
  text "YES" at 330.098,72.381 h1.52
  text "REQUIRED" at 352.208,68.542 h1.52
  text "NONE" at 340.486,68.469 h1.52
  text "X" at 348.982,68.469 h1.52
  text "PER ORDER" at 367.245,68.469 h1.52
  text "BARE BOARD ELEC. TEST:" at 307.092,68.342 h1.52
  text "MANUFACTURER'S UL:" at 307.092,64.354 h1.52
  text "METAL" at 349.422,64.373 h1.52
  text "X" at 358.953,64.364 h1.52
  text "SILK" at 362.419,64.373 h1.52
  text "RAIL" at 336.702,64.245 h1.52
M11 Gerber Information:
  lines w0.254: 10.16,16.607 177.8,16.607 ; 10.16,21.772 177.851,21.772 ; 10.16,26.937 10.16,11.443 111.887,11.443 177.851,11.443 177.851,26.937 10.173,26.937 10.173,11.443 50.19,11.443 ; 72.771,11.443 72.771,26.937 ; 104.953,21.772 104.953,26.937 ; 126.289,21.772 126.289,26.937 ; 142.088,11.278 142.088,16.43
  text "ALL ARTWORK VIEWED FROM TOP SIDE" at 11.773,23.58 h1.52
  text "BOARD #:" at 74.676,23.58 h1.52
  text ".PRJ_Number" at 88.532,23.58 h1.52
  text "REV:" at 109.982,23.58 h1.52
  text ".PCB_Rev" at 117.386,23.58 h1.52
  text "SVN REV:" at 131.267,23.58 h1.52
  text ".VersionControl_RevNumber" at 144.12,23.58 h1.52
  text "LAYER NAME =" at 11.773,18.428 h1.52
  text "PLOT NAME =" at 11.773,13.199 h1.52
  text ".plot_File_Name" at 32.233,13.199 h1.52
  text "GENERATED    :" at 74.727,13.199 h1.52
  text ".Print_Date" at 96.812,13.199 h1.52
  text ".Print_Time" at 115.329,13.199 h1.52
  text "TEXAS INSTRUMENTS" at 147.447,13.199 h1.52
M12 Stackup:
  lines w0.152: 305.105,221.59 369.875,221.59 ; 305.105,224.241 369.875,224.241 ; 303.581,209.271 ccw(c304.444,209.271) 304.444,208.407 370.535,208.407 ccw(c370.535,209.271) 371.399,209.271 371.399,227.203 ccw(c370.535,227.203) 370.535,228.067 304.444,228.067 ccw(c304.444,227.203) 303.581,227.203 303.581,209.271
  text "The Stackup Legend below this is static." at 311.34,232.118 h1.52
  text "If you change the stackup, update the Legend." at 311.594,229.832 h1.52
  text "Layer Stack Up Detail for: Ref_Design.PcbDoc" at 305.105,225.072 h1.45
  text "Layer" at 305.105,223.251 h0.61
  text "Gerber" at 327.858,223.251 h0.61
  text "Copper" at 342.172,223.251 h0.61
  text "Dielectric" at 357.481,223.251 h0.61
  text "Name" at 305.105,222.032 h0.61
  text "Document" at 327.858,222.032 h0.61
  text "Thickness" at 342.172,222.032 h0.61
  text "Material" at 357.481,222.032 h0.61
  text "Top Solder Mask" at 305.105,219.67 h0.86
  text "(.GTS)" at 327.858,219.67 h0.86
  text "Solder Resist" at 357.481,219.67 h0.86
  text ".Layer_Name" at 284.988,218.186 h1.52
  text "Top Layer" at 305.105,217.213 h0.86
  text "(.GTL)" at 327.858,217.213 h0.86
  text "1.4mil" at 342.172,217.213 h0.86
  text "FR-4" at 357.481,215.984 h0.86
  text "Bottom Layer" at 305.105,214.755 h0.86
  text "(.GBL)" at 327.858,214.755 h0.86
  text "1.4mil" at 342.172,214.755 h0.86
  text "Bottom Solder Mask" at 305.105,212.298 h0.86
  text "(.GBS)" at 327.858,212.298 h0.86
  text "Solder Resist" at 357.481,212.298 h0.86
M13 Component Bodies Top:
  text ".Layer_Name" at 157.226,138.786 h1.52
M14 Component Bodies Bottom:
  text ".Layer_Name" at 157.226,136.246 h1.52
M15 Courtyards Top:
  text ".Layer_Name" at 157.226,133.706 h1.52
M16 Courtyards Bottom:
  text ".Layer_Name" at 157.226,131.166 h1.52
Drill Drawing:
  text ".Layer_Name" at 157.226,105.766 h1.52

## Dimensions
145.136,143.358 to 151.917,158.471 on M2 Board Dimensions
28.702,143.358 to 20.218,169.037 on M2 Board Dimensions
125.705,61.646 to 151.917,58.649 on M2 Board Dimensions
20.218,58.649 to 48.997,60.96 on M2 Board Dimensions
133.706,143.358 to 145.136,143.358 on M2 Board Dimensions
28.702,143.358 to 40.132,143.358 on M2 Board Dimensions
17.577,29.807 to 42.977,29.807 on M2 Board Dimensions
75.87,72.492 to 99.238,72.492 on M2 Board Dimensions
99.238,97.13 to 99.238,72.492 on M2 Board Dimensions
99.746,71.984 to 125.705,61.646 on M2 Board Dimensions
48.997,60.96 to 75.311,71.984 on M2 Board Dimensions
48.997,60.96 to 125.705,61.646 on M2 Board Dimensions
